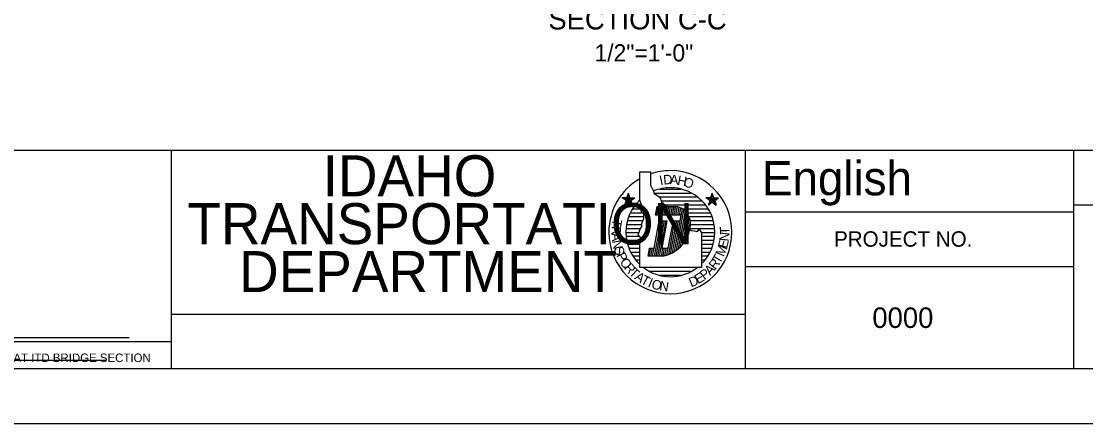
# Model space of a CAD drawing. Extents: x 0 to 68.6, y 0 to 47.1.
# Drawn here: x 25.26 to 44.72, y 0 to 7.35 of the extents above; entities that cross this region are included whole.
import ezdxf

# ---------------------------------------------------------------- set-up
doc = ezdxf.new("R2010")
doc.units = 0
for name, color, linetype in [('BORDER_ANNO_Cutsheet', 7, 'Continuous'), ('BRDG_ANNO_Anno-Large-Print', 7, 'Continuous'), ('BRDG_ANNO_Anno-Sheet', 7, 'Continuous'), ('BRDG_ANNO_Anno-Small-Print', 7, 'Continuous'), ('BRDG_ANNO_General-Notes', 7, 'Continuous')]:
    doc.layers.add(name, color=color, linetype=linetype)

msp = doc.modelspace()

# ---------------------------------------------------------------- linework, layer by layer
at = {"layer": 'BORDER_ANNO_Cutsheet'}
msp.add_lwpolyline([(0, 44), (68, 44), (68, 0), (0, 0)], close=True, dxfattribs=at)
at = {"layer": 'BRDG_ANNO_Anno-Large-Print'}
msp.add_line((23.799, 1.161), (26.811, 1.161), dxfattribs=at)
at = {"layer": 'BRDG_ANNO_Anno-Sheet'}
for p, q in [((3, 5), (38.5, 5)), ((28, 1), (28, 5)), ((38.5, 1), (38.5, 5)), ((38.5, 5), (67, 5)), ((44.5, 1), (44.5, 5)), ((36.569, 4.085), (36.569, 4.606)), ((36.569, 4.606), (36.766, 4.606)), ((36.766, 4.346), (36.766, 4.606)), ((36.766, 4.346), (36.819, 4.252)), ((36.93, 4.289), (37.316, 4.289)), ((36.402, 4.08), (36.245, 4.131)), ((36.331, 4.131), (36.245, 4.131)), ((36.315, 4.08), (36.245, 4.131)), ((36.386, 4.131), (36.288, 3.996)), ((36.315, 4.08), (36.474, 4.131)), ((36.331, 4.131), (36.359, 4.214)), ((36.331, 4.131), (36.43, 3.996)), ((36.359, 4.047), (36.359, 4.214)), ((36.386, 4.131), (36.359, 4.214)), ((36.386, 4.131), (36.474, 4.131)), ((36.402, 4.08), (36.474, 4.131)), ((36.819, 4.252), (36.829, 4.21)), ((36.829, 4.21), (36.932, 4.138)), ((36.834, 4.216), (37.501, 4.216)), ((36.93, 4.145), (37.614, 4.145)), ((36.932, 4.138), (36.965, 4.054)), ((37.935, 4.08), (37.776, 4.131)), ((37.847, 4.08), (37.776, 4.131)), ((37.864, 4.131), (37.776, 4.131)), ((37.919, 4.131), (37.82, 3.996)), ((37.847, 4.08), (38.005, 4.131)), ((37.864, 4.131), (37.891, 4.214)), ((37.864, 4.131), (37.962, 3.996)), ((37.891, 4.047), (37.891, 4.214)), ((37.919, 4.131), (37.891, 4.214)), ((37.919, 4.131), (38.005, 4.131)), ((37.935, 4.08), (38.005, 4.131)), ((36.315, 4.08), (36.288, 3.996)), ((36.359, 4.047), (36.288, 3.996)), ((36.359, 4.047), (36.43, 3.996)), ((36.402, 4.08), (36.43, 3.996)), ((36.434, 3.929), (36.585, 3.929)), ((36.484, 4.001), (36.587, 4.001)), ((36.549, 4.072), (36.572, 4.072)), ((36.589, 4.013), (36.569, 4.085)), ((36.589, 3.95), (36.589, 4.013)), ((36.589, 3.897), (36.589, 3.95)), ((36.6, 3.856), (36.589, 3.897)), ((36.85, 3.814), (36.881, 3.971)), ((36.879, 3.814), (36.907, 3.971)), ((36.881, 3.971), (37.225, 3.971)), ((36.91, 3.814), (36.94, 3.971)), ((36.942, 3.814), (36.971, 3.971)), ((36.957, 4.072), (37.701, 4.072)), ((36.965, 4.054), (37.069, 3.971)), ((36.974, 3.814), (37.004, 3.971)), ((37.005, 3.814), (37.035, 3.971)), ((37.031, 4.001), (37.765, 4.001)), ((37.038, 3.814), (37.066, 3.971)), ((37.069, 3.814), (37.099, 3.971)), ((37.101, 3.814), (37.13, 3.971)), ((37.133, 3.814), (37.163, 3.971)), ((37.165, 3.814), (37.194, 3.971)), ((37.196, 3.814), (37.226, 3.971)), ((37.199, 3.149), (37.344, 3.924)), ((37.227, 3.814), (37.256, 3.962)), ((37.235, 3.171), (37.373, 3.904)), ((37.26, 3.814), (37.286, 3.954)), ((37.291, 3.814), (37.315, 3.94)), ((37.337, 3.929), (37.815, 3.929)), ((37.847, 4.08), (37.82, 3.996)), ((37.891, 4.047), (37.82, 3.996)), ((37.891, 4.047), (37.962, 3.996)), ((37.935, 4.08), (37.962, 3.996)), ((44.5, 4), (60.5, 4)), ((36.341, 3.712), (36.623, 3.712)), ((36.362, 3.785), (36.637, 3.785)), ((36.394, 3.856), (36.596, 3.856)), ((36.641, 3.835), (36.6, 3.856)), ((36.6, 3.657), (36.62, 3.7)), ((36.62, 3.7), (36.641, 3.751)), ((36.641, 3.782), (36.641, 3.835)), ((36.641, 3.751), (36.641, 3.782)), ((36.829, 3.21), (36.922, 3.71)), ((36.832, 3.064), (36.954, 3.71)), ((37.322, 3.814), (36.85, 3.814)), ((36.865, 3.064), (36.986, 3.71)), ((36.896, 3.064), (37.017, 3.71)), ((36.922, 3.71), (37.06, 3.71)), ((36.929, 3.064), (37.05, 3.71)), ((37.06, 3.71), (36.966, 3.21)), ((37.087, 3.21), (37.181, 3.71)), ((37.094, 3.095), (37.209, 3.71)), ((37.127, 3.11), (37.24, 3.71)), ((37.163, 3.126), (37.273, 3.71)), ((37.181, 3.71), (37.304, 3.71)), ((37.273, 3.201), (37.399, 3.877)), ((37.304, 3.71), (37.322, 3.814)), ((37.311, 3.237), (37.425, 3.849)), ((37.351, 3.28), (37.45, 3.812)), ((37.394, 3.337), (37.474, 3.764)), ((37.42, 3.856), (37.855, 3.856)), ((37.465, 3.785), (37.886, 3.785)), ((37.489, 3.712), (37.909, 3.712)), ((38.5, 3.875), (44.5, 3.875)), ((36.315, 3.569), (36.581, 3.569)), ((36.325, 3.641), (36.596, 3.641)), ((36.557, 3.501), (36.569, 3.544)), ((36.569, 3.544), (36.6, 3.606)), ((36.6, 3.606), (36.6, 3.657)), ((37.444, 3.435), (37.491, 3.69)), ((37.481, 3.555), (37.496, 3.532)), ((37.485, 3.569), (37.935, 3.569)), ((37.495, 3.641), (37.925, 3.641)), ((37.496, 3.532), (37.559, 3.522)), ((37.559, 3.522), (37.621, 3.512)), ((37.621, 3.512), (37.652, 3.554)), ((37.652, 3.554), (37.694, 3.491)), ((36.312, 3.496), (36.555, 3.496)), ((36.316, 3.425), (36.562, 3.425)), ((36.326, 3.353), (36.596, 3.353)), ((36.538, 3.45), (36.557, 3.501)), ((36.569, 3.419), (36.538, 3.45)), ((36.589, 3.387), (36.569, 3.419)), ((36.569, 3.304), (36.6, 3.335)), ((36.6, 3.366), (36.589, 3.387)), ((36.6, 3.335), (36.6, 3.366)), ((37.69, 3.496), (37.938, 3.496)), ((37.694, 3.491), (37.694, 2.855)), ((37.694, 3.353), (37.924, 3.353)), ((37.695, 3.425), (37.934, 3.425)), ((36.343, 3.281), (36.567, 3.281)), ((36.367, 3.209), (36.565, 3.209)), ((36.399, 3.136), (36.565, 3.136)), ((36.569, 2.855), (36.569, 3.304)), ((36.719, 3.064), (36.746, 3.21)), ((36.737, 3.064), (36.765, 3.21)), ((36.746, 3.21), (36.829, 3.21)), ((36.77, 3.064), (36.797, 3.21)), ((36.801, 3.064), (36.829, 3.21)), ((36.96, 3.064), (36.987, 3.21)), ((36.966, 3.21), (37.087, 3.21)), ((36.992, 3.065), (37.02, 3.21)), ((37.026, 3.074), (37.051, 3.21)), ((37.06, 3.084), (37.082, 3.21)), ((37.694, 3.281), (37.907, 3.281)), ((37.694, 3.209), (37.883, 3.209)), ((37.694, 3.136), (37.85, 3.136)), ((36.44, 3.065), (36.566, 3.065)), ((36.491, 2.992), (36.565, 2.992)), ((36.555, 2.921), (36.567, 2.921)), ((36.985, 3.064), (36.719, 3.064)), ((37.694, 3.065), (37.81, 3.065)), ((37.694, 2.992), (37.76, 2.992)), ((37.694, 2.855), (36.569, 2.855)), ((37.501, 2.782), (36.744, 2.782)), ((38.5, 2.875), (44.5, 2.875)), ((37.317, 2.711), (36.935, 2.711)), ((28, 2), (38.5, 2))]:
    msp.add_line(p, q, dxfattribs=at)
msp.add_lwpolyline([(3, 43), (67, 43), (67, 1), (3, 1)], close=True, dxfattribs=at)
for centre, radius, start, end in [((37.125, 3.5), 1.125, 119.6331, 180), ((37.125, 3.5), 1.125, 90, 108.596), ((37.125, 3.5), 1.125, 0, 90), ((37.125, 3.5), 0.813, 90, 112.1452), ((37.125, 3.5), 0.813, 0, 90), ((37.125, 3.5), 0.813, 133.1926, 180), ((37.167, 3.648), 0.328, 343.4981, 79.7362), ((36.87, 3.676), 0.623, 280.6479, 348.7719), ((37.125, 3.5), 1.125, 180, 270), ((37.125, 3.5), 0.813, 180.2644, 226.7946), ((37.125, 3.5), 1.125, 270, 0), ((37.125, 3.5), 0.813, 314.427, 0), ((37.125, 3.5), 0.813, 232.5658, 270), ((37.125, 3.5), 0.813, 270, 307.4536)]:
    msp.add_arc(centre, radius, start, end, dxfattribs=at)
at = {"layer": 'BRDG_ANNO_Anno-Small-Print'}
for p, q in [((24.432, 1.573), (27.227, 1.573)), ((23, 1.5), (28, 1.5))]:
    msp.add_line(p, q, dxfattribs=at)

# ---------------------------------------------------------------- texts
at = {"layer": 'BRDG_ANNO_Anno-Sheet'}
for s, height, p in [('IDAHO', 0.75, (30.767, 4.156)), ('English', 0.625, (38.801, 4.174)), ('TRANSPORTATION', 0.75, (28.294, 3.281)), ('PROJECT NO.', 0.28125, (40.118, 3.235)), ('DEPARTMENT', 0.75, (29.239, 2.406)), ('0000', 0.375, (40.818, 1.75))]:
    msp.add_text(s, height=height, dxfattribs=at).set_placement(p)
for s, rotation, p in [('I', 11.9519, (36.944, 4.356)), ('D', 5.2118, (37.002, 4.369)), ('A', 357.8718, (37.114, 4.376)), ('H', 349.6318, (37.244, 4.367)), ('O', 342.1917, (37.349, 4.346)), ('T', 259.4265, (36.076, 3.751)), ('R', 266.0275, (36.053, 3.615)), ('T', 90.4926, (38.204, 3.459)), ('A', 273.764, (36.046, 3.481)), ('N', 280.3758, (36.057, 3.342)), ('E', 75.6105, (38.159, 3.194)), ('N', 83.1932, (38.19, 3.326)), ('S', 287.9279, (36.086, 3.208)), ('P', 295.4976, (36.131, 3.081)), ('T', 59.0362, (38.027, 2.91)), ('M', 67.7139, (38.101, 3.041)), ('O', 302.6446, (36.191, 2.96)), ('R', 309.9079, (36.267, 2.845)), ('R', 52.3344, (37.947, 2.802)), ('T', 317.1211, (36.355, 2.742)), ('A', 324.6375, (36.456, 2.651)), ('E', 30.5476, (37.631, 2.547)), ('P', 37.6656, (37.746, 2.619)), ('A', 45, (37.851, 2.701)), ('T', 331.7503, (36.569, 2.574)), ('I', 337.0213, (36.699, 2.507)), ('O', 343.3287, (36.765, 2.481)), ('N', 351.6598, (36.917, 2.44)), ('D', 22.9887, (37.506, 2.491))]:
    msp.add_text(s, height=0.174, rotation=rotation, dxfattribs=at).set_placement(p)
at = {"layer": 'BRDG_ANNO_Anno-Small-Print'}
msp.add_text('ORIGINAL STORED AT ITD BRIDGE SECTION', height=0.15643, dxfattribs=at).set_placement((23.125, 1.126))
at = {"layer": 'BRDG_ANNO_General-Notes'}
for s, height, p in [('SECTION C-C', 0.375, (34.894, 7.205)), ('1/2"=1\'-0"', 0.3125, (35.738, 6.622))]:
    msp.add_text(s, height=height, dxfattribs=at).set_placement(p)

doc.saveas('drawing.dxf')
